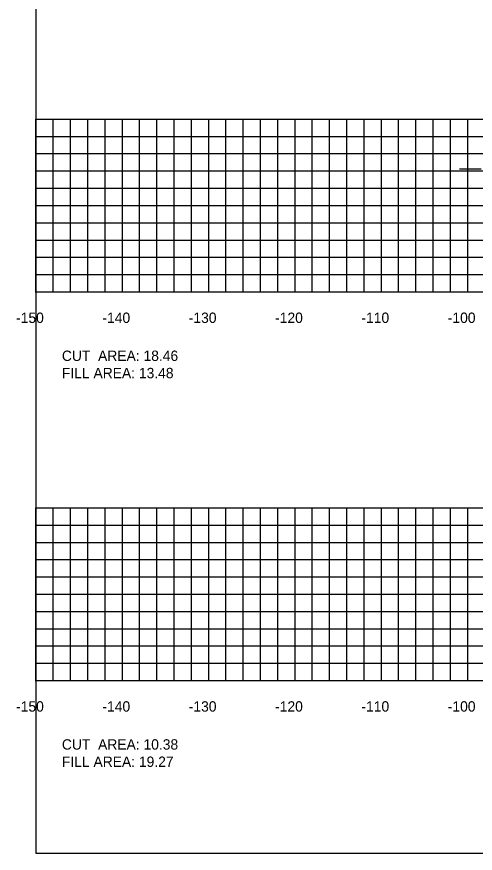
# Model space of a CAD drawing. Extents: x 1797419 to 1809236, y 248759 to 251512.
# Drawn here: x 1802138.8 to 1802191.9, y 250417.3 to 250514.1 of the extents above; entities that cross this region are included whole.
import ezdxf

# ---------------------------------------------------------------- set-up
doc = ezdxf.new("R2010")
doc.units = 0
for name, color, linetype in [('10', 7, 'Continuous'), ('60', 7, 'Continuous'), ('ANNO-TXT', 7, 'Continuous'), ('Level 62', 7, 'Continuous'), ('M-ROADS', 7, 'Continuous')]:
    doc.layers.add(name, color=color, linetype=linetype)

msp = doc.modelspace()

# ---------------------------------------------------------------- linework, layer by layer
msp.add_lwpolyline([(1802141.002, 250417.255), (1802441.002, 250417.255), (1802441.002, 250607.255), (1802141.002, 250607.255)], close=True)
at = {"layer": '60'}
for p, q in [((1802140.942, 250502.255), (1802141.002, 250502.255)), ((1802141.002, 250482.255), (1802141.002, 250502.255)), ((1802140.942, 250492.255), (1802141.002, 250492.255)), ((1802140.942, 250482.255), (1802141.002, 250482.255)), ((1802141.002, 250482.255), (1802441.002, 250482.255)), ((1802141.002, 250482.195), (1802141.002, 250482.255)), ((1802151.002, 250482.195), (1802151.002, 250482.255)), ((1802161.002, 250482.195), (1802161.002, 250482.255)), ((1802171.002, 250482.195), (1802171.002, 250482.255)), ((1802181.002, 250482.195), (1802181.002, 250482.255)), ((1802191.002, 250482.195), (1802191.002, 250482.255)), ((1802140.942, 250457.255), (1802141.002, 250457.255)), ((1802141.002, 250437.255), (1802141.002, 250457.255)), ((1802140.942, 250447.255), (1802141.002, 250447.255)), ((1802140.942, 250437.255), (1802141.002, 250437.255)), ((1802141.002, 250437.255), (1802441.002, 250437.255)), ((1802141.002, 250437.195), (1802141.002, 250437.255)), ((1802151.002, 250437.195), (1802151.002, 250437.255)), ((1802161.002, 250437.195), (1802161.002, 250437.255)), ((1802171.002, 250437.195), (1802171.002, 250437.255)), ((1802181.002, 250437.195), (1802181.002, 250437.255)), ((1802191.002, 250437.195), (1802191.002, 250437.255))]:
    msp.add_line(p, q, dxfattribs=at)
at = {"layer": 'Level 62'}
for p, q in [((1802141.002, 250502.255), (1802441.002, 250502.255)), ((1802141.002, 250482.255), (1802141.002, 250502.255)), ((1802143.002, 250482.255), (1802143.002, 250502.255)), ((1802145.002, 250482.255), (1802145.002, 250502.255)), ((1802147.002, 250482.255), (1802147.002, 250502.255)), ((1802149.002, 250482.255), (1802149.002, 250502.255)), ((1802151.002, 250482.255), (1802151.002, 250502.255)), ((1802153.002, 250482.255), (1802153.002, 250502.255)), ((1802155.002, 250482.255), (1802155.002, 250502.255)), ((1802157.002, 250482.255), (1802157.002, 250502.255)), ((1802159.002, 250482.255), (1802159.002, 250502.255)), ((1802161.002, 250482.255), (1802161.002, 250502.255)), ((1802163.002, 250482.255), (1802163.002, 250502.255)), ((1802165.002, 250482.255), (1802165.002, 250502.255)), ((1802167.002, 250482.255), (1802167.002, 250502.255)), ((1802169.002, 250482.255), (1802169.002, 250502.255)), ((1802171.002, 250482.255), (1802171.002, 250502.255)), ((1802173.002, 250482.255), (1802173.002, 250502.255)), ((1802175.002, 250482.255), (1802175.002, 250502.255)), ((1802177.002, 250482.255), (1802177.002, 250502.255)), ((1802179.002, 250482.255), (1802179.002, 250502.255)), ((1802181.002, 250482.255), (1802181.002, 250502.255)), ((1802183.002, 250482.255), (1802183.002, 250502.255)), ((1802185.002, 250482.255), (1802185.002, 250502.255)), ((1802187.002, 250482.255), (1802187.002, 250502.255)), ((1802189.002, 250482.255), (1802189.002, 250502.255)), ((1802191.002, 250482.255), (1802191.002, 250502.255)), ((1802141.002, 250500.255), (1802441.002, 250500.255)), ((1802141.002, 250498.255), (1802441.002, 250498.255)), ((1802141.002, 250496.255), (1802441.002, 250496.255)), ((1802141.002, 250494.255), (1802441.002, 250494.255)), ((1802141.002, 250492.255), (1802441.002, 250492.255)), ((1802141.002, 250490.255), (1802441.002, 250490.255)), ((1802141.002, 250488.255), (1802441.002, 250488.255)), ((1802141.002, 250486.255), (1802441.002, 250486.255)), ((1802141.002, 250484.255), (1802441.002, 250484.255)), ((1802141.002, 250482.255), (1802441.002, 250482.255)), ((1802141.002, 250457.255), (1802441.002, 250457.255)), ((1802141.002, 250437.255), (1802141.002, 250457.255)), ((1802143.002, 250437.255), (1802143.002, 250457.255)), ((1802145.002, 250437.255), (1802145.002, 250457.255)), ((1802147.002, 250437.255), (1802147.002, 250457.255)), ((1802149.002, 250437.255), (1802149.002, 250457.255)), ((1802151.002, 250437.255), (1802151.002, 250457.255)), ((1802153.002, 250437.255), (1802153.002, 250457.255)), ((1802155.002, 250437.255), (1802155.002, 250457.255)), ((1802157.002, 250437.255), (1802157.002, 250457.255)), ((1802159.002, 250437.255), (1802159.002, 250457.255)), ((1802161.002, 250437.255), (1802161.002, 250457.255)), ((1802163.002, 250437.255), (1802163.002, 250457.255)), ((1802165.002, 250437.255), (1802165.002, 250457.255)), ((1802167.002, 250437.255), (1802167.002, 250457.255)), ((1802169.002, 250437.255), (1802169.002, 250457.255)), ((1802171.002, 250437.255), (1802171.002, 250457.255)), ((1802173.002, 250437.255), (1802173.002, 250457.255)), ((1802175.002, 250437.255), (1802175.002, 250457.255)), ((1802177.002, 250437.255), (1802177.002, 250457.255)), ((1802179.002, 250437.255), (1802179.002, 250457.255)), ((1802181.002, 250437.255), (1802181.002, 250457.255)), ((1802183.002, 250437.255), (1802183.002, 250457.255)), ((1802185.002, 250437.255), (1802185.002, 250457.255)), ((1802187.002, 250437.255), (1802187.002, 250457.255)), ((1802189.002, 250437.255), (1802189.002, 250457.255)), ((1802191.002, 250437.255), (1802191.002, 250457.255)), ((1802141.002, 250455.255), (1802441.002, 250455.255)), ((1802141.002, 250453.255), (1802441.002, 250453.255)), ((1802141.002, 250451.255), (1802441.002, 250451.255)), ((1802141.002, 250449.255), (1802441.002, 250449.255)), ((1802141.002, 250447.255), (1802441.002, 250447.255)), ((1802141.002, 250445.255), (1802441.002, 250445.255)), ((1802141.002, 250443.255), (1802441.002, 250443.255)), ((1802141.002, 250441.255), (1802441.002, 250441.255)), ((1802141.002, 250439.255), (1802441.002, 250439.255)), ((1802141.002, 250437.255), (1802441.002, 250437.255))]:
    msp.add_line(p, q, dxfattribs=at)
at = {"layer": 'M-ROADS'}
msp.add_lwpolyline([(1802190.069, 250496.495), (1802190.269, 250496.495), (1802192.546, 250496.495)], dxfattribs=at)

# ---------------------------------------------------------------- texts
at = {"layer": '10'}
for s, p in [('-150', (1802138.698, 250478.655)), ('-140', (1802148.698, 250478.655)), ('-130', (1802158.698, 250478.655)), ('-120', (1802168.698, 250478.655)), ('-110', (1802178.698, 250478.655)), ('-100', (1802188.698, 250478.655)), ('-150', (1802138.698, 250433.655)), ('-140', (1802148.698, 250433.655)), ('-130', (1802158.698, 250433.655)), ('-120', (1802168.698, 250433.655)), ('-110', (1802178.698, 250433.655)), ('-100', (1802188.698, 250433.655))]:
    msp.add_text(s, height=1.2, dxfattribs=at).set_placement(p)
at = {"layer": '60'}
for p in [(1802141.002, 250482.255), (1802141.002, 250437.255)]:
    msp.add_text('-', height=0.0001, dxfattribs=at).set_placement(p)
at = {"layer": 'ANNO-TXT'}
for s, p in [('CUT  AREA: 18.46', (1802144.002, 250474.255)), ('FILL AREA: 13.48', (1802144.002, 250472.255)), ('CUT  AREA: 10.38', (1802144.002, 250429.255)), ('FILL AREA: 19.27', (1802144.002, 250427.255))]:
    msp.add_text(s, height=1.2, dxfattribs=at).set_placement(p)

doc.saveas('drawing.dxf')
